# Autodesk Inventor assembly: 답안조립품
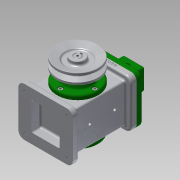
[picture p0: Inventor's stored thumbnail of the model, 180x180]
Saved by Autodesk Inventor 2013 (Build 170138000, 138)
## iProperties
Created: 2017-08
Part Number: 답안조립품
Document SubType Name: Assembly
Designer: Administrator
Author: Administrator
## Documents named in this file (16)
- C:\Users\Administrator\Desktop\470808V1012\답안조립품.iam
- C:\Users\Administrator\Desktop\470808V1012\본체.ipt
- C:\Users\Administrator\Desktop\470808V1012\편심축.ipt
- C:\Users\Administrator\Desktop\470808V1012\베어링 17 x 40 x 12.ipt
- C:\Users\Administrator\Desktop\470808V1012\뒤커버.ipt
- C:\Users\Administrator\Desktop\470808V1012\볼트 M4 x 8.ipt
- C:\Users\Administrator\Desktop\470808V1012\앞커버.ipt
- C:\Users\Administrator\Desktop\470808V1012\슬라이더.ipt
- C:\Users\Administrator\Desktop\470808V1012\링크.ipt
- C:\Users\Administrator\Desktop\470808V1012\클레비스 핀 6 x 22.ipt
- 클레비스 핀 6 x 22.ipt
- C:\Users\Administrator\Desktop\470808V1012\E-링.ipt
- C:\Users\Administrator\Desktop\470808V1012\덮개.ipt
- C:\Users\Administrator\Desktop\470808V1012\오일 실 17 30 8.ipt
- C:\Users\Administrator\Desktop\470808V1012\V-벨트풀리.ipt
- C:\Users\Administrator\Desktop\470808V1012\키 4 x 4 x 12.ipt
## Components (2 placed, 2 different names)
1. E-링:1
2. V-벨트풀리:1
